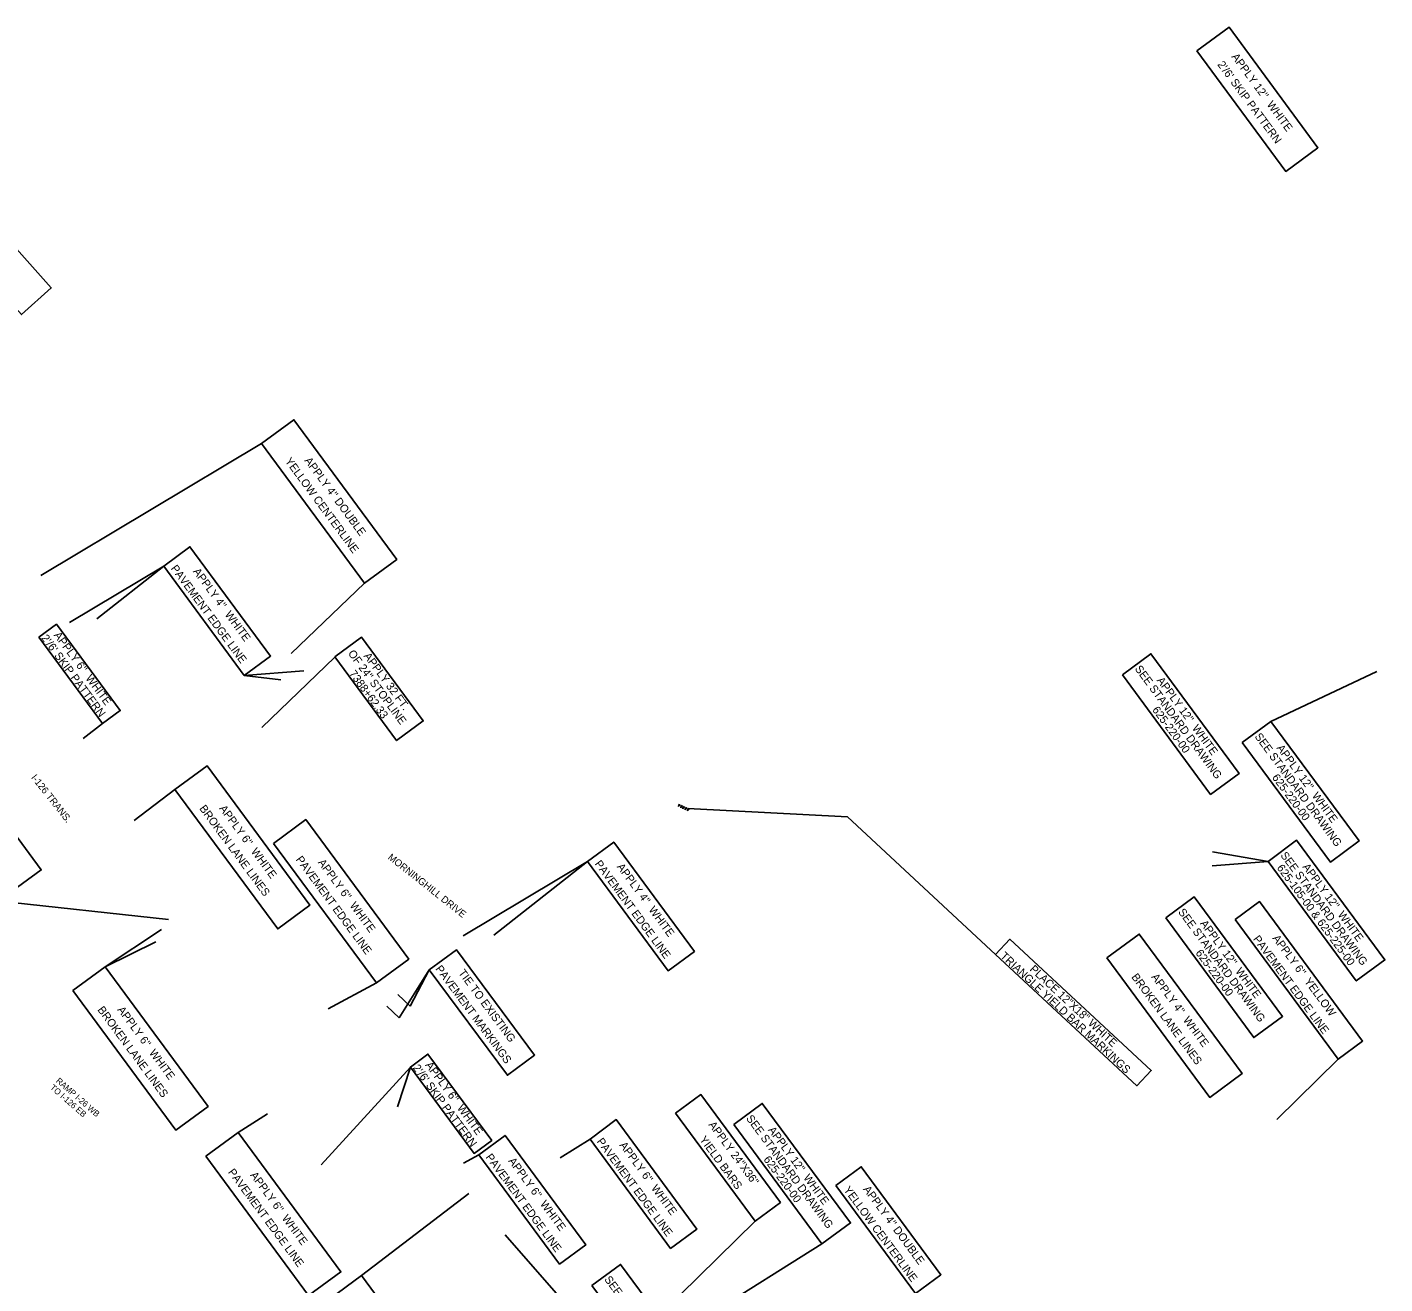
# Model space of a CAD drawing. Extents: x 1966013 to 1974896, y 789499 to 804826.
# Drawn here: x 1969854 to 1971211, y 797178 to 798435 of the extents above; entities that cross this region are included whole.
import ezdxf

# ---------------------------------------------------------------- set-up
doc = ezdxf.new("R2010")
doc.units = 0
for name, color, linetype in [('RD_EX_H2O_BlueLn', 7, 'Continuous'), ('RD_PD_ALT1_LnLine', 7, 'Continuous'), ('RD_PD_Final_Cl', 7, 'Continuous'), ('RD_PD_Final_LnLine', 7, 'Continuous'), ('RD_PD_MedBWall', 7, 'Continuous')]:
    doc.layers.add(name, color=color, linetype=linetype)

msp = doc.modelspace()

# ---------------------------------------------------------------- linework, layer by layer
at = {"layer": 'RD_EX_H2O_BlueLn'}
for p, q in [((1969867.7, 797886.4), (1970088.6, 798018.3)), ((1969896.4, 797839.5), (1969990.7, 797895.8)), ((1969923.9, 797843.2), (1969990.7, 797895.8)), ((1970118.2, 797808.3), (1970191.5, 797878.8)), ((1970088.7, 797734.3), (1970161.9, 797804.8)), ((1971097.6, 797740.5), (1971203.4, 797790.3)), ((1969910.1, 797723.3), (1969929.6, 797738.3)), ((1969961.2, 797641.3), (1970001.8, 797672.5)), ((1971039.1, 797609.9), (1971094.7, 797600.5)), ((1970290, 797526.1), (1970414.4, 797600.5)), ((1970320.8, 797526.6), (1970414.4, 797600.5)), ((1971039, 797596), (1971094.7, 797600.5)), ((1969781, 797565.7), (1969995.6, 797542.2)), ((1969932.2, 797494.9), (1969988.4, 797532.4)), ((1969932.2, 797494.9), (1969982.9, 797520.1)), ((1970226.2, 797443.9), (1970256.2, 797492)), ((1970237.1, 797455.6), (1970256.2, 797492)), ((1970155.2, 797453.1), (1970203.4, 797479)), ((1970237.1, 797455.6), (1970224.9, 797467.2)), ((1970226.2, 797443.9), (1970213.9, 797455.7)), ((1971164.9, 797402.8), (1971103.5, 797342.4)), ((1970148, 797296.9), (1970237.3, 797394.8)), ((1970224.3, 797355.1), (1970237.3, 797394.8)), ((1970065, 797329.5), (1970094.6, 797347.9)), ((1970386.9, 797304.1), (1970416.9, 797322.8)), ((1970290.3, 797298.8), (1970305.7, 797307.1)), ((1970188.6, 797186.4), (1970295.7, 797268.4)), ((1970507, 797167), (1970581.9, 797240.7)), ((1970521.6, 797138.2), (1970648.7, 797217.9))]:
    msp.add_line(p, q, dxfattribs=at)
for points in [[(1971023.6, 798411), (1971112.4, 798290.5), (1971144.6, 798314.2), (1971055.8, 798434.8)], [(1969732.9, 798276.6), (1969848.4, 798147.3), (1969878.2, 798174), (1969762.8, 798303.3)], [(1970088.6, 798018.3), (1970191.5, 797878.8), (1970223.6, 797902.5), (1970120.8, 798042.1)], [(1969990.7, 797895.8), (1970071.3, 797786.5), (1970097.5, 797805.8), (1970016.9, 797915.2)], [(1969865.9, 797824.7), (1969929.6, 797738.3), (1969947.3, 797751.3), (1969883.5, 797837.7)], [(1970161.8, 797804.9), (1970223.5, 797721.3), (1970250.2, 797741), (1970188.6, 797824.6)], [(1970949.1, 797787), (1971037.3, 797667.4), (1971065.9, 797688.5), (1970977.7, 797808.1)], [(1971069, 797719.4), (1971157.1, 797599.8), (1971185.7, 797620.9), (1971097.6, 797740.5)], [(1969733.2, 797707.7), (1969836, 797568.2), (1969868.2, 797591.9), (1969765.4, 797731.4)], [(1970001.8, 797672.5), (1970104.7, 797533), (1970136.9, 797556.7), (1970034, 797696.2)], [(1970100.5, 797618.5), (1970203.4, 797479), (1970235.6, 797502.7), (1970132.7, 797642.2)], [(1970414.4, 797600.5), (1970495, 797491.1), (1970521.2, 797510.4), (1970440.6, 797619.8)], [(1971094.7, 797600.5), (1971182.9, 797481), (1971211.5, 797502), (1971123.3, 797621.6)], [(1970992.4, 797543.9), (1971080.5, 797424.3), (1971109.2, 797445.4), (1971021, 797565)], [(1971062, 797542.3), (1971164.9, 797402.8), (1971189.2, 797420.7), (1971086.3, 797560.2)], [(1970822.3, 797507.2), (1970963.6, 797376.1), (1970977.9, 797391.4), (1970836.5, 797522.6)], [(1970933.7, 797504), (1971036.5, 797364.5), (1971068.7, 797388.2), (1970965.9, 797527.7)], [(1970256.2, 797492), (1970334.3, 797386.6), (1970361.4, 797406.7), (1970283.4, 797512.1)], [(1969900, 797471.2), (1970002.9, 797331.6), (1970035.1, 797355.4), (1969932.2, 797494.9)], [(1970237.3, 797394.8), (1970301, 797308.4), (1970318.7, 797321.4), (1970254.9, 797407.8)], [(1970502.4, 797348.6), (1970581.9, 797240.7), (1970607.3, 797259.4), (1970527.7, 797367.3)], [(1970560.5, 797337.4), (1970648.7, 797217.9), (1970677.3, 797239), (1970589.1, 797358.5)], [(1970416.9, 797322.8), (1970497.5, 797213.4), (1970523.7, 797232.8), (1970443.1, 797342.2)], [(1970032.8, 797305.8), (1970135.6, 797166.3), (1970167.8, 797190), (1970065, 797329.5)], [(1970305.7, 797307.1), (1970386.4, 797197.7), (1970412.6, 797217), (1970332, 797326.4)], [(1970662.7, 797276.4), (1970742.3, 797168.4), (1970767.6, 797187.1), (1970688.1, 797295.1)], [(1970418.8, 797176.4), (1970506.9, 797056.8), (1970535.6, 797077.9), (1970447.4, 797197.5)], [(1970156.4, 797162.6), (1970259.2, 797023.1), (1970291.4, 797046.8), (1970188.6, 797186.4)]]:
    msp.add_lwpolyline(points, close=True, dxfattribs=at)
for points in [[(1970071.3, 797786.5), (1970130.7, 797791)], [(1970071.3, 797786.5), (1970107.7, 797782.2)], [(1970514.7, 797653.2), (1970674.4, 797645), (1970822.3, 797507.2)]]:
    msp.add_lwpolyline(points, dxfattribs=at)
at = {"layer": 'RD_PD_ALT1_LnLine'}
for p, q in [((1970505.3, 797655.2), (1970505.6, 797657.5)), ((1970507, 797656.9), (1970505.3, 797655.2)), ((1970505.6, 797657.5), (1970507, 797656.9)), ((1970507.6, 797654.1), (1970507.9, 797656.5)), ((1970507.9, 797656.5), (1970509.2, 797655.8)), ((1970509.2, 797655.8), (1970507.6, 797654.1)), ((1970509.8, 797653.1), (1970510.1, 797655.4)), ((1970511.4, 797654.8), (1970509.8, 797653.1)), ((1970510.1, 797655.4), (1970511.4, 797654.8)), ((1970512.1, 797652), (1970512.4, 797654.3)), ((1970513.8, 797653.7), (1970512.1, 797652)), ((1970512.4, 797654.3), (1970513.8, 797653.7)), ((1970514.3, 797651), (1970514.6, 797653.4)), ((1970516, 797652.7), (1970514.3, 797651)), ((1970514.6, 797653.4), (1970516, 797652.7))]:
    msp.add_line(p, q, dxfattribs=at)
at = {"layer": 'RD_PD_Final_LnLine'}
msp.add_line((1970331.9, 797227), (1970484.2, 797053.2), dxfattribs=at)

# ---------------------------------------------------------------- texts
at = {"layer": 'RD_EX_H2O_BlueLn'}
for s, height, rotation, p in [("APPLY 12''  WHITE", 7.999, 306.3979, (1971057.8, 798405.1)), ("2'/6' SKIP PATTERN", 7.999, 306.3979, (1971043.7, 798397.3)), ('YELLOW CENTERLINE', 7.999, 306.3977, (1970111.5, 798000.7)), ("APPLY 4'' DOUBLE", 7.999, 306.3977, (1970131, 798001.2)), ('PAVEMENT EDGE LINE', 8, 306.3977, (1969997.4, 797893.4)), ("APPLY 4''  WHITE", 8, 306.3977, (1970019.6, 797890.3)), ("2'/6' SKIP PATTERN", 7.999, 306.3978, (1969867.9, 797823.8)), ("APPLY 6''  WHITE", 7.999, 306.3978, (1969880.4, 797826.6)), ('OF 24" STOPLINE', 7.999, 306.3977, (1970174.5, 797808.4)), ('APPLY 32 FT.', 7.999, 306.3977, (1970190.2, 797805.8)), ('7388+62.33', 8, 306.3977, (1970175.6, 797788.1)), ('SEE STANDARD DRAWING', 8, 306.3977, (1970961.1, 797793)), ("APPLY 12''  WHITE", 8, 306.3977, (1970983.1, 797781.4)), ('625-220-00 ', 8, 306.3977, (1970978.5, 797751.9)), ('SEE STANDARD DRAWING', 8, 306.3977, (1971080.9, 797725.3)), ("APPLY 12''  WHITE", 8, 306.3977, (1971102.9, 797713.8)), ('625-220-00 ', 8, 306.3977, (1971098.3, 797684.3)), ('BROKEN LANE LINES', 8, 306.3977, (1970025.9, 797653.3)), ("APPLY 6''  WHITE", 8, 306.3977, (1970045.8, 797653.3)), ('PAVEMENT EDGE LINE', 8, 306.3977, (1970122.4, 797602.3)), ('PAVEMENT EDGE LINE', 8, 306.3977, (1970421.2, 797598)), ('SEE STANDARD DRAWING', 8, 306.3977, (1971106.7, 797606.5)), ("APPLY 6''  WHITE", 8, 306.3977, (1970144.5, 797599.3)), ("APPLY 4''  WHITE", 8, 306.3977, (1970443.3, 797595)), ('625-105-00 & 625-225-00', 8, 306.3977, (1971103.1, 797593.9)), ("APPLY 12''  WHITE", 8, 306.3977, (1971128.7, 797594.9)), ('SEE STANDARD DRAWING', 8, 306.3977, (1971004.4, 797549.8)), ("APPLY 12''  WHITE", 8, 306.3977, (1971026.4, 797538.3)), ('PAVEMENT EDGE LINE', 8, 306.3977, (1971079.3, 797522.8)), ("APPLY 6''  YELLOW", 8, 306.3977, (1971098.7, 797523.5)), ('TRIANGLE YIELD BAR MARKINGS', 7.999, 317.1328, (1970826.4, 797504.9)), ('625-220-00 ', 8, 306.3977, (1971021.8, 797508.8)), ('PAVEMENT MARKINGS', 8, 306.5163, (1970261.9, 797492.9)), ('TIE TO EXISTING', 8, 306.5163, (1970284.8, 797488.9)), ('PLACE 12"X18" WHITE', 7.999, 317.1328, (1970855.8, 797491.8)), ('BROKEN LANE LINES', 8, 306.3977, (1970957.7, 797484.8)), ("APPLY 4''  WHITE", 8, 306.3977, (1970977.6, 797484.8)), ('BROKEN LANE LINES', 8, 306.3977, (1969924.1, 797452)), ("APPLY 6''  WHITE", 8, 306.3977, (1969944, 797452)), ("APPLY 6''  WHITE", 7.999, 306.3978, (1970251.8, 797396.7)), ("2'/6' SKIP PATTERN", 7.999, 306.3978, (1970239.3, 797393.9)), ('SEE STANDARD DRAWING', 8, 306.3977, (1970572.5, 797343.4)), ('APPLY 24"X36"', 7.999, 306.3977, (1970534.9, 797337)), ("APPLY 12''  WHITE", 8, 306.3977, (1970594.5, 797331.8)), ('PAVEMENT EDGE LINE', 8, 306.3977, (1970423.2, 797320.3)), ("APPLY 6''  WHITE", 8, 306.3977, (1970445.9, 797316.6)), ('YIELD BARS', 8, 306.3977, (1970525.9, 797322.3)), ('PAVEMENT EDGE LINE', 8, 306.3977, (1970312.1, 797304.6)), ('625-220-00 ', 8, 306.3977, (1970589.9, 797302.3)), ('PAVEMENT EDGE LINE', 8, 306.3977, (1970054.6, 797289.6)), ("APPLY 6''  WHITE", 8, 306.3977, (1970334.8, 797300.8)), ("APPLY 6''  WHITE", 8, 306.3977, (1970076.7, 797286.6)), ('YELLOW CENTERLINE', 7.999, 306.3977, (1970670, 797272)), ("APPLY 4'' DOUBLE", 7.999, 306.3977, (1970689.5, 797272.5)), ('SEE STANDARD DRAWING', 8, 306.3977, (1970430.8, 797182.4))]:
    msp.add_text(s, height=height, rotation=rotation, dxfattribs=at).set_placement(p)
at = {"layer": 'RD_PD_Final_Cl'}
msp.add_text('I-126 TRANS.', height=7, rotation=308.3228, dxfattribs=at).set_placement((1969857.7, 797684.1))
at = {"layer": 'RD_PD_MedBWall'}
for s, height, rotation, p in [('MORNINGHILL DRIVE', 7, 321.5853, (1970214.2, 797603.4)), ('TO I-126 EB ', 6, 318.8475, (1969876.6, 797373.5)), ('RAMP I-26 WB ', 6, 318.8475, (1969882.5, 797380.2))]:
    msp.add_text(s, height=height, rotation=rotation, dxfattribs=at).set_placement(p)

doc.saveas('drawing.dxf')
